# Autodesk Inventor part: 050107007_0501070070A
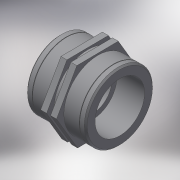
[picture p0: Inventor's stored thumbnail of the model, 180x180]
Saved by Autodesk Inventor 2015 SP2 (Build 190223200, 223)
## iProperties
Created: 2017-05
Part Number: 050107007_0501070070A
Material: Generic
Description: PLASSON SOCKET PP 3/4"-3/4"
Document SubType Name: Modeling
Designer: KIM
Density: 1 g/cm^3
Appearance: Default
Author: KIM
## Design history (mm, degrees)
derived "050107.ipt"
feature "Solid1::050107.ipt"
tag "TaggingFeature1"
body "Solid1"
other parameters: "d0" = 41, "d2" = 24.117, "d3" = 19, "d5" = 36, "d6" = 34.2, "d7" = 19.2936, "d14" = 0, "d15" = 0.72351, "d18" = 4.1, "d19" = 1.36667, "d20" = 0.5, "d21" = 0.5, "d22" = 34.2, "Rp_" = 24.117, "H_" = 41, "l_2" = 19, "E_" = 36
